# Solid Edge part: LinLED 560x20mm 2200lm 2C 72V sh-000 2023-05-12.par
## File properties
Author: jaroslaw.przewlocki
Template: iso metric part.par
Last saved by: jaroslaw.przewlocki
Revision: 1
Application: Solid Edge
Gęstość: 0,000 kg/m^3
Dokładność: 0,990
Username: jaroslaw.przewlocki
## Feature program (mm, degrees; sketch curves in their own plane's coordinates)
body "unnamed Body 1"
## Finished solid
Body 1: solid body, 1718 faces, 4486 edges, 2932 vertices.
  Faces by surface: plane 1398, cylinder 164, torus 64, cone 50, spline 26, sphere 16
  Edges by curve: line 3810, curve on surface 356, circle 218, ellipse 66, spline 36
Bounding box of the edges (mm; curved faces can reach further): 559.600 x 20.000 x 4.450, from (-279.8, -10, -1) to (279.8, 10, 3.45).
Cylindrical faces by radius (mm): R0.2 x46, R0.2169 x6, R0.25 x32, R0.3373 x6, R0.4 x8, R0.4006 x2, R0.4008 x2, R0.525 x2, R0.6 x20, R1 x12, R1.1 x4, R1.1989 x2, R1.199 x2, R1.2 x10, R2.15 x10
Conical faces (half-angle, radius in mm at the cone's reference point): 0.398 deg R1.1964 x2, 0.4493 deg R1.1964 x2, 0.4746 deg R1.1948 x2, 0.4758 deg R1.1948 x2, 0.5 deg R0.5056 x4, 0.5 deg R1.0082 x4, 1 deg R0.5511 x2, 10 deg R0.2132 x4, 10 deg R0.4132 x4, 16.0099 deg R1.1053 x2, 16.1249 deg R1.1279 x2, 18.8604 deg R1.0669 x4, 19.5041 deg R0.5138 x2, 19.8244 deg R0.5099 x2, 27.363 deg R0.6214 x2, 40.6434 deg R0.5161 x2, 43.3309 deg R0.4892 x2, 45 deg R0.575 x2, 45 deg R0.625 x4
Toroidal faces (ring radius, tube radius in mm): R0.0958 r0.3997 x4, R0.1076 r0.4 x2, R0.1101 r0.4001 x2, R0.1217 r0.4 x2, R0.1234 r0.4 x2, R0.1626 r0.228 x2, R0.1634 r0.2287 x2, R0.3287 r0.2001 x2, R0.3684 r0.2151 x2, R0.3703 r0.4 x2, R0.3818 r0.2 x4, R0.4166 r0.3983 x2, R0.5981 r0.197 x2, R0.5982 r0.197 x2, R0.6009 r0.3968 x2, R0.6009 r0.3969 x2, R0.6227 r0.2 x2, R0.6235 r0.2 x2, R0.8 r0.2 x4, R0.8522 r0.3 x2, R0.9002 r0.2 x2, R0.9018 r0.2 x2, R0.9197 r0.223 x2, R0.9365 r0.2 x2, R0.9663 r0.2263 x2, R0.9665 r0.2263 x2, R1.429 r1.2 x2, R1.8741 r0.2175 x2, R1.9007 r0.2 x2
Spherical faces by radius (mm): R0.2 x12, R0.6 x4
Planar faces by outward normal: +x 170, +y 175, +z 241, -x 170, -y 177, -z 9, oblique 456
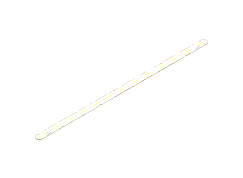
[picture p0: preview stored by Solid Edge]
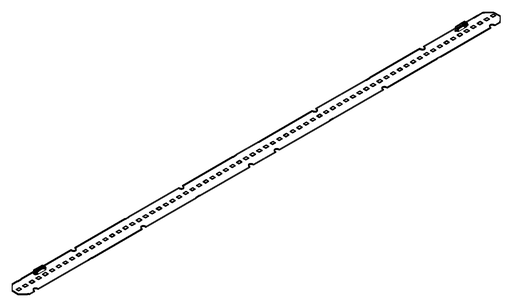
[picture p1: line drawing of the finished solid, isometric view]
